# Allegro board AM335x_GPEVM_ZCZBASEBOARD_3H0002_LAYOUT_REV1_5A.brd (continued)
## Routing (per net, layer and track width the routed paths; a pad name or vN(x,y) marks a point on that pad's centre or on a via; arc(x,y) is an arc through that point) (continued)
DDR_A10: length 61
  TOP w0.102: U2.F4 v2(81.8,80.2)
  TOP w0.121: U33.H7 v1(92.98,59.04) ; U34.H7 v1(78.38,59.04)
  LY4 w0.076: 87.29,58 87.54,58 87.69,58.15 93.15,58.15 93.24,58.24
  LY4 w0.133: v1(92.98,59.04) 93.24,58.77 93.24,58.24 ; 87.29,58 85.58,58 85.11,58.47 84.64,58.47 84.63,58.48 82.28,58.48 82.03,58.74 82.03,59.63 81.77,59.89 78.52,59.89 78.38,59.74 v1(78.38,59.04)
  BOTTOM w0.076: 93.68,55.54 93.66,55.56 93.66,56.71 93.3,57.07 92.83,57.07 92.61,57.28 92.61,58.67 v1(92.98,59.04)
  BOTTOM w0.121: R614.2 95.26,54.88 95.26,55.18 95.14,55.31 93.91,55.31 93.68,55.54 ; v1(78.38,59.04) 78.75,59.4 79.01,59.4 79.89,60.29 80.48,60.29 83.35,63.16 84.24,63.16 84.54,63.46 84.54,65.75 84.8,66 86.09,66 86.22,66.13 86.22,67.3 86.09,67.42 84.14,67.42 84.01,67.3 84.01,67.18 83.88,67.05 83,67.05 82.77,67.28 82.4,67.28 82.31,67.19 80.2,67.19 79.69,67.7 79.69,69.18 79.88,69.37 79.88,69.64 80.05,69.8 80.05,74.3 79.92,74.42 79.83,74.42 79.7,74.55 79.7,76.65 80.46,77.4 80.51,77.4 82.21,79.09 82.21,79.79 81.8,80.2 v2(81.8,80.2)
DDR_A11: length 60.8
  TOP w0.121: v1(74.38,59.04) U34.M7 ; U2.F2 82.43,78.77 82.43,78.75 82.58,78.61 82.58,77.63 82.38,77.43 82.38,72.61 82.51,72.49 v1(82.51,72.05) ; v1(88.98,59.04) U33.M7
  LY4 w0.076: 87.29,59.09 87.62,59.09 87.82,58.89 88.84,58.89 v1(88.98,59.04)
  LY4 w0.127: v1(74.38,59.04) 74.1,59.31
  LY4 w0.133: 74.1,59.31 74.1,59.96 74.23,60.08 76.9,60.08 77.02,60.21 77.02,60.69 77.15,60.81 83.07,60.81 83.2,60.69 83.2,59.65 83.32,59.52 85.56,59.52 86,59.09 87.29,59.09 ; v1(72.5,67.5) 72.5,68.46 72.74,68.7 73.12,68.7 73.12,68.71 74.88,68.71 75.5,68.08 75.81,68.08 76.44,68.72 77.5,68.72 79.1,70.32 79.1,70.33 79.74,70.98 82.05,70.98 82.51,71.43 v1(82.51,72.05)
  BOTTOM w0.121: v1(88.98,59.04) 88.59,59.04 88.5,58.94 87.44,58.94 87.31,58.81 87.31,58.69 86.24,57.62 86.24,55.26 R615.2 ; v1(74.38,59.04) 74.38,59.81 73.95,60.24 71.14,60.24 69.2,62.18 69.2,65.31 69.77,65.88 70.88,65.88 v1(72.5,67.5)
DDR_A12: length 61.6
  TOP w0.102: v2(81,79.4) U2.E3
  TOP w0.121: v1(90.58,59.04) U33.K7 ; v1(75.98,59.04) U34.K7
  LY4 w0.076: v1(90.58,59.04) 90.95,59.04 91.02,58.97 91.02,58.62 90.89,58.49 87.58,58.49 87.51,58.56 87.29,58.56
  LY4 w0.133: v1(75.98,59.04) 76.26,59.31 76.47,59.52 77.51,59.52 77.63,59.65 77.63,60.23 77.76,60.36 82.34,60.36 82.66,60.03 82.66,59.12 82.79,58.99 85.36,58.99 85.78,58.56 87.2,58.56 87.2,58.56 87.29,58.56
  BOTTOM w0.121: v1(90.58,59.04) 89.95,58.41 87.9,58.41 87.21,57.72 87.21,54.98 R616.2 ; v1(75.98,59.04) 75.7,59.31 75.7,59.66 74.31,61.04 74.21,61.04 73.98,61.27 73.98,62.54 73.77,62.75 71.08,62.75 70,63.83 70,64.86 70.26,65.12 70.76,65.12 70.89,65 70.89,64.78 71.02,64.65 72.59,64.65 72.71,64.78 72.71,66.49 73.02,66.79 74.26,66.79 74.73,67.27 74.73,68.45 75.16,68.87 75.16,68.88 75.61,69.33 76.7,69.33 77.09,68.94 77.46,68.94 77.78,69.26 77.78,69.51 77.46,69.83 77.46,70.33 79.14,72 79.14,73.14 78.29,73.98 78.29,76.39 81,79.1 v2(81,79.4)
DDR_A13: length 61
  TOP w0.102: U2.H3 v2(83.4,79.4)
  TOP w0.121: v1(88.18,62.24) U33.N3 ; v1(73.58,61.44) U34.N3
  LY4 w0.076: v1(88.18,62.24) 87.81,62.6 87.81,63.39 87.54,63.66 ; v1(73.58,61.44) 73.95,61.8 73.95,62.32 74.22,62.6 74.47,62.6 75.55,63.68 75.55,63.68 75.98,64.12
  LY4 w0.133: 75.98,64.12 76.27,64.41 76.3,64.41 76.39,64.5 78.14,64.5 79.2,65.56 85.64,65.56 87.54,63.66 ; v1(73.58,61.44) 73.12,61.89 73.12,64 73.8,64.68 73.98,64.68 74.99,65.7 76.87,65.7 78.27,67.09 79.23,67.09 79.51,67.37 79.51,67.92 80.03,68.44 v1(80.48,68.44)
  BOTTOM w0.076: v1(88.18,62.24) 88.61,62.66 88.61,64.02
  BOTTOM w0.121: v1(80.48,68.44) 80.95,68.91 81.51,68.91 81.64,69.04 81.64,69.53 81.77,69.66 82.52,69.66 82.65,69.53 82.65,68.82 82.78,68.69 85.94,68.69 86.07,68.82 86.07,69.35 83.79,71.63 83.79,71.74 83,72.53 82.54,72.53 82.41,72.66 82.41,74.87 82.28,74.99 81.03,74.99 80.9,75.12 80.9,75.34 80.9,75.34 80.9,75.71 80.9,75.71 80.9,75.72 81.49,76.31 81.49,77 83.4,78.9 v2(83.4,79.4) ; 88.61,64.02 88.34,64.29 87.96,64.29 87.57,64.68 87.29,64.68 87.03,64.93 87.03,65.55 87.37,65.89 87.37,65.91 87.67,66.2 R617.2
DDR_A14: length 61.6
  TOP w0.102: v2(83.4,80.2) U2.H4
  TOP w0.121: v1(88.05,59.35) 88.31,59.09 88.31,58.9 U33.N7 ; v1(81.34,75.53) 81.01,75.2 81.01,74.18 79.29,72.45 v1(78.07,72.45) ; v1(73.58,59.04) U34.N7
  LY4 w0.076: 87.42,59.35 87.29,59.35
  LY4 w0.127: v1(88.05,59.35) 87.42,59.35 ; 73.3,59.31 v1(73.58,59.04)
  LY4 w0.133: 87.29,59.35 86.11,59.35 85.65,59.8 83.58,59.8 83.45,59.93 83.45,60.91 83.34,61.02 76.88,61.02 76.77,60.91 76.77,60.62 76.74,60.58 76.74,60.58 76.5,60.35 76.03,60.35 75.91,60.46 73.43,60.46 73.3,60.34 73.3,59.31
  BOTTOM w0.121: R618.2 84.49,55.08 84.62,55.21 85.84,55.21 85.97,55.33 85.97,57.77 87.54,59.35 v1(88.05,59.35) ; v2(83.4,80.2) 83.4,80.19 83.79,79.79 83.79,79.56 83.79,79.06 83.7,78.97 83.7,78.56 82.05,76.91 82.05,76.24 v1(81.34,75.53)
  BOTTOM w0.127: v1(73.58,59.04) 71.87,59.04 71.84,59.07 71.44,59.07 67.91,62.6 67.91,65.59 69.94,67.63 70.27,67.63 71.09,68.45 73.26,68.45 74.28,69.47 74.28,69.64 75.44,70.8 76.41,70.8 v1(78.07,72.45)
DDR_A15: length 62.1
  TOP w0.102: v2(80.2,79.4) U2.D3
  TOP w0.121: U34.J7 v1(76.78,59.04) 76.14,59.68 73.18,59.68 69.63,63.23 v1(68.46,63.23) ; v1(91.38,59.04) U33.J7
  LY4 w0.076: 91.88,58.44 91.76,58.31 87.62,58.31 87.62,58.3 87.29,58.3 87.29,58.3
  LY4 w0.133: v1(91.38,59.04) 91.76,59.04 91.88,58.91 91.88,58.44 ; 87.29,58.3 85.68,58.3 85.25,58.73 82.64,58.73 82.38,58.99 82.38,59.7 81.95,60.14 78.04,60.14 77.91,60.01 77.91,59.16 77.79,59.04 v1(76.78,59.04)
  BOTTOM w0.121: v1(91.38,59.04) 90.78,58.43 90.46,58.43 90.23,58.2 90.21,58.2 90.19,58.17 88.35,58.17 87.59,57.42 87.59,55.61 R619.2 ; v1(68.46,63.23) 68.46,65.72 69.99,67.25 70.4,67.25 71.35,68.2 73.37,68.2 75.35,70.18 76.48,70.18 78.63,72.33 78.63,72.83 78.5,72.96 78.06,72.96 77.68,73.34 77.68,76.72 79.59,78.62 79.72,78.62 80.2,79.11 v2(80.2,79.4)
DDR_BA0: length 62.5
  TOP w0.102: U2.C4 v1(79.4,80.2)
  TOP w0.121: v1(93.51,65.14) 94.27,65.14 94.4,65.26 94.4,65.7 R620.2 ; v1(76.78,62.24) U34.J2 77.61,63.07 77.61,64.93 77.16,65.38 74.85,65.38 73.37,66.86 73.37,68.13 72.94,68.56 v1(72.94,69.15) ; U33.J2 v1(91.38,62.24)
  LY4 w0.076: 84.53,63.23 80.38,63.23 80.22,63.38 80.22,63.69 80.17,63.74 79.92,63.74 79.13,62.95 77.54,62.95 77.24,62.65 77.19,62.65 v1(76.78,62.24) ; 92.49,64.58 91.93,64.02 91.93,63.61 91.38,63.06 v1(91.38,62.24) 90.97,62.24 90.84,62.11 90.84,61.81 90.97,61.68 90.97,61.24 90.84,61.11 90.79,61.11 90.6,60.92 87.42,60.92 87.4,60.95
  LY4 w0.127: 84.59,63.24 84.54,63.24 84.53,63.23
  LY4 w0.133: 87.4,60.95 86.95,60.95 86.32,61.58 85.69,61.58 85.3,61.96 85.3,62.84 84.85,63.29 84.63,63.29 84.59,63.24 ; v1(93.51,65.14) 94.02,65.14 94.14,65.01 94.14,64.8 94.02,64.67 93.6,64.67 93.51,64.58 92.49,64.58
  BOTTOM w0.121: v1(79.4,80.2) 78.85,80.2 78.5,79.85 76.46,79.85 75.9,79.29 75.9,78.39 74.41,76.9 74.23,76.9 73.44,77.68 73.26,77.68 73.08,77.5 73.08,77.32 73.87,76.54 73.87,76.36 73.69,76.18 73.51,76.18 72.76,76.93 72.58,76.93 72.4,76.75 72.4,76.57 73.15,75.82 73.15,75.64 72.94,75.42 72.94,74.82 72.81,74.69 71.54,74.69 71.41,74.57 71.41,74.31 71.54,74.19 72.81,74.19 72.94,74.06 72.94,73.8 72.81,73.68 71.82,73.68 71.69,73.55 71.69,73.3 71.82,73.17 72.81,73.17 72.94,73.04 v1(72.94,69.15)
DDR_BA1: length 60.9
  TOP w0.121: v1(90.58,57.44) U33.K8 ; v1(75.6,68.69) 75.6,69.14 76.28,69.81 76.28,70.29 76.4,70.42 80.73,70.42 80.86,70.55 80.86,70.75 80.73,70.88 76.92,70.88 76.8,71 76.8,71.16 76.92,71.28 77.35,71.28 77.61,71.54 77.61,72.77 77.74,72.9 78.89,72.9 80.71,74.71 80.71,75.52 81.16,75.97 81.16,75.98 81.4,76.22 U2.E1 ; v1(75.98,57.44) U34.K8
  LY4 w0.133: v1(90.58,57.44) 90.98,57.04 90.98,56.47 90.98,56.47 90.98,55.52 90.61,55.16 82.49,55.16 82.05,55.59 80.07,55.59 78.62,57.03 76.38,57.03 v1(75.98,57.44)
  BOTTOM w0.076: v1(90.58,57.44) 90.21,57.44 90.16,57.49 90.16,57.9 90.28,58.03 90.89,58.03 91.01,57.9 91.01,57.28 91.01,56.48 91.03,56.46 91.03,55.58 91.07,55.54
  BOTTOM w0.121: v1(75.98,57.44) 76.37,57.83 76.37,58.87 76.37,58.87 76.37,59.2 76.36,59.2 76.36,59.5 74.77,61.09 74.77,61.58 74.78,61.59 74.78,61.6 75.01,61.83 75.05,61.83 75.06,61.84 75.3,61.84 75.3,61.84 75.34,61.84 75.58,62.08 75.58,62.4 76.08,62.9 76.08,64.1 76.64,64.65 76.64,65.04 75.07,66.61 75.07,68.16 v1(75.6,68.69) ; R621.2 92.87,55.03 92.67,55.23 91.38,55.23 91.07,55.54
DDR_BA2: length 61.1
  TOP w0.121: U2.B3 79,79.52 78.59,79.11 78.59,77.99 78.1,77.51 75.69,77.51 74.61,77.51 74.15,77.05 73.16,77.05 71.61,75.5 71.61,72.6 71.36,72.35 68.43,72.35 68.18,72.1 68.18,65.65 73.57,60.26 76.62,60.26 76.78,60.41 v1(76.78,61.44) U34.J3 ; R622.2 94.91,65.42 v1(93.76,64.27) ; v1(91.38,61.44) U33.J3
  LY4 w0.076: 77.15,61.81 77.15,62.33 77.6,62.78 79.23,62.78 79.49,63.03 84.62,63.03 ; 93.28,64.27 92.85,64.27 91.76,63.18 91.76,62.14 91.75,62.13 91.75,62.08 91.38,61.71 v1(91.38,61.44) 91.38,61.07 91.48,60.97 91.48,60.5 91.35,60.37 90.79,60.37 90.47,60.69 87.29,60.69
  LY4 w0.127: 77.15,61.81 v1(76.78,61.44) ; 84.75,63.03 84.62,63.03
  LY4 w0.133: 87.29,60.69 86.84,60.69 86.21,61.32 85.58,61.32 84.97,61.92 84.97,62.8 84.75,63.03 ; v1(93.76,64.27) 93.28,64.27
DDR_CASN: length 61.2
  TOP w0.121: v1(78.38,61.44) U34.G3 ; U2.F1 82.2,77.76 82.13,77.69 82.13,75.14 82.06,75.08 82.06,72 81.94,71.87 79.74,71.87 79.62,71.74 79.62,71.51 79.74,71.39 82.63,71.39 82.76,71.26 82.76,70.19 82.63,70.06 81.9,70.06 81.77,69.94 81.77,69.51 81.9,69.38 82.52,69.38 82.65,69.25 82.65,68.5 82.57,68.42 82.57,67.87 82.45,67.74 79.82,67.74 79.69,67.87 79.69,68.57 79.56,68.69 79.17,68.69 79.04,68.57 v1(79.04,67.78) ; v1(92.98,61.44) U33.G3
  LY4 w0.076: 87.29,59.9 89.71,59.9 89.9,60.1 90.36,60.1 90.58,59.88 92.72,59.88
  LY4 w0.127: 81.19,61.83 79.81,61.83 79.42,61.44 v1(78.38,61.44)
  LY4 w0.133: v1(92.98,61.44) 92.98,60.14 92.72,59.88 ; 81.19,61.83 81.32,61.96 81.32,62.11 81.44,62.24 82.61,62.24 82.74,62.11 82.74,61.96 82.87,61.83 83.86,61.83 83.98,61.7 83.98,60.54 84.11,60.41 86.02,60.41 86.14,60.29 86.14,60.11 86.35,59.9 87.29,59.9
  BOTTOM w0.076: v1(92.98,61.44) 93.35,61.44 93.41,61.49 93.41,62.48 93.53,62.6 93.69,62.6 93.81,62.73 93.81,63.78 93.69,63.91 93.46,63.91 93.33,64.03 93.33,64.46 93.55,64.68 93.56,64.68
  BOTTOM w0.121: 93.56,64.68 93.57,64.7 93.69,64.7 93.95,64.95 93.95,65.32 93.69,65.58 93.5,65.58 R601.2 ; v1(78.38,61.44) 78.42,61.44 78.97,61.99 78.97,62 79,62.02 79,62.64 79.01,62.65 79.01,66.13 79.14,66.25 81.98,66.25 82.1,66.38 82.1,66.81 81.98,66.94 79.14,66.94 79.04,67.04 v1(79.04,67.78)
DDR_CKE: length 62.1
  TOP w0.102: U2.G3 v2(82.6,79.4)
  TOP w0.121: U33.G9 93.71,57.04 93.81,56.93 93.81,56.04 93.69,55.92 93.11,55.92 92.98,56.04 v1(92.98,56.64) ; U34.G9 v1(78.38,56.64) ; R635.2 71.67,58.43 v1(72.35,58.43)
  LY4 w0.127: v1(80.33,69.45) 79.63,69.45 79.63,69.46 79.39,69.46 78.04,68.11 76.82,68.11 76.16,67.45 74.74,67.45
  LY4 w0.133: 74.74,67.45 72.35,65.06 v1(72.35,58.43) 72.35,58.1 73.18,57.27 73.18,57.27 73.41,57.04 73.74,57.04 73.97,56.8 73.97,56.48 74.21,56.24 77.22,56.24 77.62,56.64 v1(78.38,56.64) 79.73,55.28 81.8,55.28 82.22,54.87 91.21,54.87 92.7,56.36 v1(92.98,56.64)
  BOTTOM w0.076: v1(92.98,56.64) 93.35,56.64 93.46,56.53 93.46,55.97 93.26,55.76 93.26,55.58 93.21,55.54
  BOTTOM w0.121: v1(80.33,69.45) 80.33,76.13 80.36,76.17 80.36,76.8 81.6,78.03 81.6,78.03 82.6,79.04 v2(82.6,79.4) ; v1(78.38,56.64) 78.65,56.36 78.65,55.29 R631.1 ; R598.2 93.99,54.42 94.22,54.42 94.35,54.55 94.35,54.93 94.22,55.06 93.26,55.06
  BOTTOM w0.127: 93.21,55.54 93.08,55.4 93.08,55.24 93.26,55.06
DDR_CLK: length 61
  TOP w0.076: 79.56,63.81 79.55,63.8 79.46,63.8 79.22,63.56 79.22,61.65 79.21,61.64 79.21,61.57 79.27,61.51 79.27,61.49
  TOP w0.095: 79.56,63.81 79.66,63.91 79.66,64.06 80.07,64.47 80.07,64.56 80.17,64.67 80.17,66.15 79.79,66.53 78.61,66.53 78.41,66.74 78.03,66.74 77.89,66.88 77.89,68.48 77.42,68.95 76.78,68.95 76.31,68.48 76.31,66.5 76.15,66.33 75.41,66.33 74.66,67.08 74.66,68.47 74.08,69.05 74.08,69.58 74.41,69.91 75.58,69.91 75.81,70.14 75.81,71.85 75.94,71.99 76.88,71.99 77.35,72.47 77.35,73.81 77.7,74.15 79.16,74.15 79.89,74.89 79.89,75.2 80.28,75.58 80.28,77.03 80.48,77.23 80.48,77.43 81.01,77.96 81.01,78.59 U2.D2 ; U34.F7 v1(79.98,59.04) 79.77,59.24 79.77,60.55 79.27,61.05 79.27,61.49 ; R624.2 100.07,59.52 99.94,59.52 99.81,59.39 99.81,59.37 99.68,59.24 99.15,59.24 99.03,59.37 99.03,59.45 98.9,59.57 95.19,59.57 94.86,59.25 94.79,59.25 v1(94.58,59.04) 94.58,59.02 94.2,58.64 U33.F7
  LY4 w0.076: 87.45,57.06 87.45,57.25 87.78,57.58 87.78,57.61 88.01,57.83 93.39,57.83 93.39,57.83 93.92,57.83
  LY4 w0.102: v1(79.98,59.04) 79.96,59.05 79.96,59.25 80.09,59.37 80.59,59.37 80.71,59.25 80.71,58.86 80.56,58.71 80.56,58.56 80.71,58.41 80.71,58.31 81.03,57.98 84.29,57.98 85.36,56.92 87.31,56.92 87.45,57.06 ; v1(94.58,59.04) 94.33,58.79 94.33,58.24 93.92,57.83
DDR_CLKN: length 61.2
  TOP w0.076: 78.99,61.49 78.99,61.51 79.06,61.57 79.06,61.7 79.07,61.71 79.07,63.62 79.35,63.9 79.35,63.99 79.36,64.01
  TOP w0.095: U34.G7 v1(79.18,59.04) 79.49,59.35 79.49,60.44 78.99,60.93 78.99,61.49 ; U33.G7 v1(93.78,59.04) 94.27,59.53 94.74,59.53 95.06,59.85 95.06,59.87 95.07,59.87 99.13,59.87 99.2,59.8 99.69,59.8 100,60.11 R625.2 ; U2.D1 80.6,77.95 80.2,77.54 80.2,77.38 79.97,77.15 79.75,77.15 79.56,76.96 79.56,76.39 79.69,76.26 79.84,76.26 79.97,76.14 79.97,75.67 79.61,75.31 79.61,75.01 79.04,74.43 77.58,74.43 77.08,73.93 77.08,72.58 76.76,72.27 75.82,72.27 75.53,71.97 75.53,70.29 75.42,70.19 74.29,70.19 73.8,69.7 73.8,68.93 74.38,68.35 74.38,66.97 75.3,66.05 76.26,66.05 76.59,66.38 76.59,68.36 76.9,68.67 77.3,68.67 77.61,68.36 77.61,66.76 77.91,66.46 78.29,66.46 78.49,66.25 79.68,66.25 79.89,66.04 79.89,64.78 79.79,64.68 79.79,64.59 79.38,64.18 79.38,64.03 79.36,64.01
  LY4 w0.076: 87.24,57.28 87.25,57.29 87.27,57.29 87.63,57.65 87.63,57.67 87.94,57.99 93.45,57.99 93.45,57.98 93.65,57.98 93.71,58.05
  LY4 w0.102: 87.24,57.28 87.18,57.23 85.48,57.23 84.42,58.29 81.16,58.29 81.01,58.43 81.01,59.4 80.72,59.69 79.7,59.69 79.44,59.43 79.44,59.3 79.35,59.21 79.35,59.21 v1(79.18,59.04) ; v1(93.78,59.04) 94.03,58.79 94.03,58.37 93.71,58.05
DDR_CSN0: length 62.3
  TOP w0.121: U2.H2 83.82,79 84.17,78.65 84.17,75.54 84.52,75.19 84.52,73.52 84.39,73.39 83.84,73.39 83.72,73.27 83.72,71.08 83.84,70.95 84.39,70.95 84.52,70.83 84.52,70.55 84.39,70.42 83.84,70.42 83.72,70.29 83.72,69.88 83.84,69.75 v1(84.45,69.75) ; U33.H2 v1(92.18,62.24) ; v1(73.95,67.6) 73.95,66.83 75.15,65.63 77.61,65.63 78.07,65.18 78.07,64.4 78.29,64.17 78.29,62.95 U34.H2 v1(77.58,62.24)
  LY4 w0.076: 84.57,62.78 79.54,62.78 79.41,62.65 79.41,62.42 79.29,62.29 78.84,62.29 78.53,62.6 77.95,62.6 v1(77.58,62.24) ; 91.76,61.81 91.76,60.57 91.41,60.22 90.66,60.22 90.47,60.42 87.84,60.42 87.84,60.42 87.29,60.42
  LY4 w0.127: 86.75,60.42 86.75,60.42 87.13,60.42 ; 91.76,61.81 v1(92.18,62.24)
  LY4 w0.133: 84.57,62.78 84.7,62.65 84.7,61.84 85.47,61.06 86.11,61.06 86.73,60.43 86.74,60.43 86.75,60.42 87.29,60.42 ; v1(84.45,69.75) 84.77,70.07 84.77,70.78 84.57,70.98 84.01,70.98 83.88,70.85 83.88,69.86 83.43,69.4 82.59,69.4 81.47,70.52 79.79,70.52 77.68,68.41 76.75,68.41 76.14,67.8 75.32,67.8 75.07,68.06 74.41,68.06 v1(73.95,67.6)
  BOTTOM w0.076: v1(92.18,62.24) 91.81,61.86 90.79,61.86 90.66,61.99 90.66,62.6 90.95,62.88 90.95,63.99 90.66,64.27 90.66,64.55 90.79,64.68 90.91,64.68
  BOTTOM w0.121: R599.2 91.35,65.7 91.35,65.12
  BOTTOM w0.127: 90.91,64.68 91.35,65.12
DDR_D0: length 35.3
  TOP w0.102: v2(87.4,79.4) U2.M3
  TOP w0.121: U33.B3 v1(97.78,61.44)
  BOTTOM w0.121: v2(87.4,79.4) 87.4,77.34 87.72,77.02 87.72,75.11 88.16,74.66 89.92,74.66 91.43,73.16 91.43,69.48 91.68,69.23 94.64,69.23 94.87,69 94.87,67.47 95.12,67.22 95.64,67.22 95.9,67.47 95.9,68.92 96.15,69.18 96.5,69.18 96.96,68.71 96.96,67.07 96.71,66.81 95.85,66.81 95.59,66.56 95.59,66.17 95.85,65.91 97.12,65.91 97.25,65.78 97.38,65.78 99.73,63.44 99.73,62.24 98.93,61.44 v1(97.78,61.44)
DDR_D1: length 35.9
  TOP w0.102: v2(87.4,80.2) U2.M4
  TOP w0.121: v1(96.98,59.04) U33.C7 ; v1(91.92,71.11) 92.37,71.11 92.39,71.08 v1(94.25,71.08)
  BOTTOM w0.121: v1(91.92,71.11) 91.92,73.02 89.8,75.14 89.8,76.17 89.1,76.87 88.56,76.87 87.79,77.63 87.79,79.79 87.4,80.19 v2(87.4,80.2) ; v1(94.25,71.08) 97.93,71.08 98.56,70.45 98.56,66.66 99.63,65.59 100.19,65.59 101.36,64.43 101.36,60.24 100.65,59.52 97.47,59.52 v1(96.98,59.04)
DDR_D2: length 35.4
  TOP w0.121: U2.N1 87.8,77.27 88.19,76.87 89.11,76.87 89.9,76.08 90.11,76.08 95.41,70.78 95.44,70.78 95.9,70.32 96.63,70.32 98.69,68.26 98.69,65.24 98.94,64.98 99.66,64.98 99.91,65.24 99.91,68.97 100.16,69.23 100.72,69.23 100.98,68.97 100.98,63.23 100.72,62.98 96.93,62.98 U33.C2
DDR_D3: length 35.8
  TOP w0.121: v1(96.98,57.44) U33.C8
  TOP w0.127: v1(99.33,67.02) 99.33,68.15 96.7,70.78 95.81,70.78 90.09,76.51 89.84,76.51 89.22,77.13 89.21,77.13 89.09,77.25 88.76,77.25 88.26,77.75 88.26,78.05 88.26,78.06 88.26,78.54 U2.N2
  BOTTOM w0.127: v1(99.33,67.02) 101.53,67.02 102.09,66.46 102.09,58.33 101.54,57.77 101.21,57.77 100.7,57.26 99.57,57.26 98.58,58.25 97.41,58.25 96.98,57.83 v1(96.98,57.44)
DDR_D4: length 35.9
  TOP w0.102: U2.N3 v2(88.2,79.4)
  TOP w0.127: U33.E3 93.97,60.82 93.97,60.26 94.3,59.93 94.68,59.93 95.38,60.63 v1(95.38,61.44)
  BOTTOM w0.121: v2(88.2,79.4) 88.2,78.18 90.21,76.17 90.21,75.37 92.37,73.21 92.37,69.61 92.47,69.51 96.53,69.51 97.22,68.82 97.22,66.38 100.09,63.51 100.09,62.19 98.77,60.87 97.78,60.87 97.52,61.12 97.52,61.14 96.55,62.11 95.82,62.11 95.66,61.96 95.66,61.71 v1(95.38,61.44)
DDR_D5: length 35.8
  TOP w0.102: U2.N4 v2(88.2,80.2)
  TOP w0.121: v1(95.38,57.44) U33.E8
  BOTTOM w0.121: v1(95.38,57.44) 94.98,57.83 94.98,59.22 95.9,60.13 95.9,61 96.15,61.25 96.58,61.25 97.27,60.57 99.15,60.57 100.39,61.8 100.39,63.59 97.57,66.41 97.57,68.95 96.46,70.06 93.48,70.06 92.7,70.85 92.7,73.49 91.81,74.38 91.81,75.21 88.59,78.42 88.59,79.81 v2(88.2,80.2)
DDR_D6: length 35.3
  TOP w0.121: v1(96.33,60.78) 96.33,61.15 96.18,61.3 96.18,62.24 U33.D2
  TOP w0.305: U2.P3 v2(89,79.4)
  BOTTOM w0.121: v2(89,79.4) 89,78.59 92.11,75.48 92.11,74.66 92.52,74.26 93.92,74.26 94.3,73.87 94.3,72.94 94.07,72.71 93.26,72.71 92.98,72.43 92.98,71.13 93.79,70.32 97.17,70.32 97.89,69.59 97.89,67.01 97.89,66.59 97.9,66.58 97.9,66.48 100.03,64.36 100.7,63.69 100.7,60.77 100.16,60.24 96.87,60.24 v1(96.33,60.78)
DDR_D7: length 35.9
  TOP w0.102: U2.P4 v2(89,80.2)
  TOP w0.121: v1(95.38,59.04) U33.E7
  BOTTOM w0.121: v2(89,80.2) 89.39,79.81 89.39,78.64 90.78,77.25 90.78,77.24 92.54,75.48 92.54,75.2 93.22,74.52 94.08,74.52 94.68,73.93 94.68,72.73 94.32,72.38 93.92,72.38 93.38,71.84 93.38,71.26 94.07,70.57 97.49,70.57 98.14,69.92 98.14,66.7 101.05,63.79 101.05,60.54 100.44,59.93 96.28,59.93 v1(95.38,59.04)
DDR_D8: length 35.4
  TOP w0.121: U2.J1 84.6,77.64 84.54,77.58 84.54,75.65 84.9,75.3 84.9,73.24 84.77,73.11 84.14,73.11 84.01,72.99 84.01,72.63 84.14,72.5 84.9,72.5 85.03,72.38 85.03,72.05 84.9,71.92 84.11,71.92 83.98,71.79 83.98,71.41 84.11,71.28 84.92,71.28 85.05,71.16 85.05,69.43 84.92,69.31 83.83,69.31 83.7,69.18 83.7,66.48 83.58,66.36 82.13,66.36 82,66.48 82,67.32 81.88,67.45 81.19,67.45 81.06,67.32 81.06,65.39 81.19,65.26 83.58,65.26 83.7,65.14 83.7,64.96 83.58,64.83 81.24,64.83 81.11,64.71 81.11,64.55 81.24,64.43 84.24,64.43 84.37,64.3 84.37,63.49 83.98,63.1 82.78,63.1 82.45,62.77 82.45,62.5 82.78,62.17 U34.B3
DDR_D9: length 35.8
  TOP w0.121: v1(90.89,70.4) 89.7,70.4 88.24,68.93 88.22,68.93 87.42,68.14 87.42,67.26 86.93,66.77 86.93,65.37 87.21,65.09 87.21,59.92 87.08,59.79 86.91,59.79 86.78,59.67 86.78,57.09 86.65,56.96 85.05,56.96 84.92,57.09 84.92,59.02 84.8,59.14 83.98,59.14 83.91,59.22 82.13,59.22 81.98,59.07 U34.C7
  TOP w0.127: U2.K1 85.4,77.96 85.6,77.77 85.6,77.76 85.65,77.71 85.65,77.68 85.7,77.63 85.7,76.1 85.25,75.65 85.25,74.1 86.7,72.66 v1(87.32,72.66)
  BOTTOM w0.127: v1(87.32,72.66) 88.11,71.87 89.83,71.87 89.95,71.74 89.95,70.52 90.08,70.4 v1(90.89,70.4)
DDR_D10: length 35.4
  TOP w0.121: U34.C2 82.23,62.38 82.23,62.13 82.41,61.95 82.41,61.28 82.54,61.15 84.49,61.15 84.62,61.28 84.62,64.65 84.49,64.78 84.19,64.78 84.06,64.91 84.06,65.44 83.93,65.57 81.52,65.57 81.39,65.7 81.39,65.9 81.52,66.03 83.93,66.03 84.06,66.15 84.06,68.92 84.19,69.05 85.2,69.05 85.33,69.18 85.33,72.86 85.46,72.99 85.89,72.99 86.01,72.86 86.01,72.45 86.14,72.32 87.03,72.32 87.14,72.21 87.51,72.21 87.62,72.32 88.38,72.32 88.51,72.45 88.51,73.29 88.38,73.42 86.3,73.42 85.51,74.21 85.51,75.51 85.64,75.64 85.84,75.64 85.96,75.77 85.96,77.69 85.88,77.77 85.88,77.81 85.83,77.86 85.83,78.59 85.41,79 U2.K2
DDR_D11: length 35.7
  TOP w0.102: v2(85.8,79.4) U2.K3
  TOP w0.121: U34.C8 82.37,58.23 84.26,58.23 84.39,58.1 84.39,56.53 84.52,56.4 87.18,56.4 87.31,56.53 87.31,58.33 87.59,58.61 87.59,59.63 87.72,59.75 87.72,65.42 87.46,65.68 87.46,66.48 87.98,67 87.98,67.19 87.98,67.98 88.43,68.43 88.72,68.43 v1(89.77,69.48)
  BOTTOM w0.121: v1(89.77,69.48) 88.35,69.48 86.44,71.39 86.44,71.5 86.37,71.57 86.37,73.05 86.37,73.05 86.37,73.79 86.59,74 86.59,74.44 86.37,74.66 86.37,74.74 85.71,75.4 85.53,75.4 84.81,76.12 84.81,76.63 85.76,77.58 85.76,78.97 85.8,79.01 v2(85.8,79.4)
DDR_D12: length 35.8
  TOP w0.102: U2.K4 v2(85.8,80.2)
  TOP w0.121: U34.E3 80.38,60.06 80.5,59.93 84.59,59.93 84.64,59.98 85.56,59.98 85.69,59.85 85.89,59.85 86.02,59.98 86.02,59.98 86.09,60.06 86.09,66.84 85.89,67.04 85.89,67.91 86.01,68.02 86.01,68.03 88.08,70.1 88.31,70.1 88.53,70.33 v1(88.53,70.78)
  BOTTOM w0.121: v2(85.8,80.2) 85.86,80.2 86.21,79.86 86.21,79.56 86.21,77.68 85.95,77.43 85.95,75.96 86.88,75.03 86.88,74.87 87.1,74.65 87.1,73.9 87.2,73.8 87.51,73.8 87.64,73.67 87.64,73.27 87.51,73.14 87.1,73.14 86.88,72.92 86.88,72.84 86.88,72.84 86.88,71.79 87.12,71.54 89.55,71.54 89.67,71.41 89.67,70.4 89.55,70.27 89.04,70.27 v1(88.53,70.78)
DDR_D13: length 35.9
  TOP w0.102: v2(86.6,79.4) U2.L3
  TOP w0.121: v1(90.41,70.85) 89.78,70.85 88.52,69.6 88.29,69.6 86.52,67.82 86.52,67.43 86.67,67.27 86.67,65.27 86.96,64.98 86.96,60.17 86.83,60.05 86.8,60.05 86.52,59.77 86.52,57.85 86.4,57.72 85.3,57.72 85.18,57.85 85.18,59.32 85.05,59.45 81.32,59.45 80.78,58.91 80.78,58.24 U34.E8
  BOTTOM w0.121: v1(90.41,70.85) 90.41,71.72 89.79,72.34 89.45,72.34 89.32,72.47 89.32,73.6 89.19,73.72 88.38,73.72 88.02,74.08 88.02,74.08 87.13,74.97 87.13,76.44 87.01,76.57 86.73,76.57 86.6,76.69 v2(86.6,79.4)
DDR_D14: length 35.9
  TOP w0.102: U2.L4 v2(86.6,80.2)
  TOP w0.127: v1(82.21,68.85) 82.21,68.4 81.8,67.99 80.29,67.99 80.03,68.26 80.03,68.62 80.04,68.63 80.04,68.85 79.91,68.97 78.72,68.97 78.6,68.85 78.6,67.59 79.12,67.07 80.56,67.07 80.68,66.94 80.68,64.3 80.38,64 80.38,63.91 80.19,63.71 80.12,63.71 80,63.59 80,63.16 80.1,63.05 80.76,63.05 U34.D2
  LY4 w0.133: v1(82.21,68.85) 86.3,68.85 87.06,69.61 87.06,70.5 88.61,72.05 88.61,72.33 88.6,72.34 88.6,73.01 88.72,73.14 v1(89.88,73.14)
  BOTTOM w0.121: v1(89.88,73.14) 90.61,73.14 90.74,73.27 90.74,73.49 89.82,74.41 88.06,74.41 87.46,75 87.46,76.92 87.15,77.24 87.15,77.24 87.01,77.38 87.01,79.79 v2(86.6,80.2)
DDR_D15: length 35.8
  TOP w0.121: U34.E7 80.38,58.96 80.43,59.01 80.43,59.47 80.69,59.73 85.3,59.73 85.43,59.6 85.43,58.28 85.56,58.15 86.14,58.15 86.27,58.28 86.27,59.88 86.42,60.03 86.42,67.17 86.26,67.32 86.26,67.92 88.19,69.85 88.41,69.85 89.67,71.11 89.67,71.11 90.13,71.56 92.09,71.56 92.21,71.69 92.21,72.98 90.69,74.51 88.91,74.51 87.97,74.51 87.44,75.03 87.44,76.71 87,77.16 U2.M1
DDR_DQM0: length 35.6
  TOP w0.121: v1(97.78,59.04) U33.B7
  TOP w0.127: v1(93.89,71.67) 90.79,74.76 88.88,74.76 88.88,74.76 88.68,74.76 88.68,74.76 88.07,74.76 87.7,75.14 87.7,77.01 87.39,77.31 87.39,78.87 87.27,79 U2.M2
  BOTTOM w0.121: v1(93.89,71.67) 94.35,71.67 94.68,71.33 98.3,71.33 98.82,70.81 98.82,66.79 99.22,66.38 101.18,66.38 101.74,65.82 101.74,59.78 100.85,58.89 98.32,58.89 98.18,59.04 v1(97.78,59.04)
DDR_DQM1: length 35.9
  TOP w0.121: U34.B7 83.09,58.95 83.71,58.95 83.92,58.74 84.54,58.74 84.67,58.61 84.67,56.76 84.77,56.65 86.93,56.65 87.03,56.76 87.03,58.57 87.16,58.69 87.26,58.69 87.39,58.82 87.39,59.71 87.46,59.79 87.46,65.21 87.18,65.5 87.18,66.66 87.73,67.21 87.73,68.09 88.33,68.68 88.34,68.68 89.65,69.98 90.23,69.98 90.53,69.68 v1(90.54,69.68)
  TOP w0.127: v1(85.25,76.3) 85.25,76.95 85.44,77.13 85.44,77.56 85.42,77.58 85.42,77.62 85,78.04 85,78.59 84.6,78.99 U2.J2
  BOTTOM w0.121: v1(90.54,69.68) 90.22,70 88.19,70 88.05,70.14 88.05,71.16 87.92,71.28 87.02,71.28 86.62,71.68 86.62,72.94 86.63,72.95 86.63,73.65 86.84,73.86 86.84,74.55 86.63,74.76 86.63,74.93 85.7,75.85 85.7,75.86 v1(85.25,76.3)
DDR_DQS0: length 35.6
  TOP w0.095: U2.P1 88.6,77.83 88.81,77.62 89.06,77.62 89.21,77.47 89.33,77.47 89.39,77.41 89.41,77.41 90.02,76.8 90.56,76.8 93.13,74.23 94.98,74.23 95.39,73.82 95.39,71.94 96.02,71.31 101.21,71.31 102.73,69.79 102.73,63.5 101.52,62.29 100.29,62.29 99.74,61.75 99.45,61.75 99.33,61.62 99.33,61.33 99.1,61.1 98.59,61.1 98.46,60.97 98.46,60.72 98.34,60.59 98.06,60.59 97.93,60.72 97.93,60.9 97.8,61.02 97.6,61.02 97.47,60.9 97.47,60.72 97.34,60.59 97.08,60.59 96.94,60.74 96.94,60.92 96.82,61.04 96.82,61.25 96.99,61.42 96.99,62.17 96.87,62.29 96.7,62.29 96.58,62.17 U33.C3
DDR_DQS1: length 35.3
  TOP w0.095: U2.L1 86.2,77.85 86.34,77.7 86.34,76.88 86.37,76.85 86.37,76.84 86.68,76.53 86.68,76.36 86.55,76.24 86.45,76.24 86.32,76.11 86.32,75.83 86.45,75.7 86.55,75.7 86.68,75.58 86.68,75.37 86.55,75.25 86.3,75.25 86.17,75.12 86.17,74.94 86.3,74.81 86.55,74.81 86.68,74.69 86.68,74.33 87.18,73.82 90.52,73.82 91.3,73.05 91.3,72.42 91.19,72.3 89.51,72.3 88.82,71.61 86.76,71.61 86.73,71.59 86.45,71.31 86.45,70.75 86.75,70.45 86.99,70.45 87.08,70.35 87.08,70.03 86.97,69.91 86.18,69.91 85.89,69.62 85.89,68.89 85.67,68.67 84.73,68.67 84.44,68.38 84.44,65.87 84.8,65.52 85.28,65.52 85.41,65.39 85.41,60.84 85.28,60.72 81.66,60.72 81.48,60.9 81.48,61.69 81.62,61.84 U34.C3
DDR_DQSN0: length 35.9
  TOP w0.095: U33.D3 95.78,61.5 95.8,61.48 95.8,60.69 96.18,60.31 98.72,60.31 100.42,62.01 101.64,62.01 103.01,63.38 103.01,69.9 101.32,71.59 96.14,71.59 95.67,72.06 95.67,73.94 95.1,74.51 93.24,74.51 90.68,77.08 90.13,77.08 89.6,77.61 89.6,77.66 89.42,77.83 89.4,77.83 89.38,77.85 89.29,77.85 89.09,78.05 89.09,78.07 89.07,78.09 89.07,78.53 U2.P2
DDR_DQSN1: length 35.7
  TOP w0.095: U2.L2 86.63,78.57 86.63,76.97 86.98,76.62 86.98,74.42 87.3,74.1 90.64,74.1 91.58,73.16 91.58,72.3 91.3,72.02 89.63,72.02 88.91,71.31 86.85,71.31 86.73,71.19 86.73,70.86 86.84,70.75 87.08,70.75 87.36,70.47 87.36,69.91 87.08,69.63 86.3,69.63 86.17,69.51 86.17,68.77 85.79,68.39 84.85,68.39 84.72,68.26 84.72,65.99 84.91,65.8 85.4,65.8 85.69,65.51 85.69,60.73 85.4,60.44 81.55,60.44 81.18,60.81 U34.D3
DDR_ODT: length 59
  TOP w0.121: U2.G1 83,77.82 82.94,77.77 82.94,77.23 82.64,76.92 82.64,73.6 82.83,73.42 82.83,72.62 83.01,72.43 83.01,70.05 83.02,70.05 83.02,68.68 83.02,68.68 v1(83.02,68.24) ; v1(88.12,64.68) 88.4,64.4 92.41,64.4 v1(92.98,63.84) U33.G1
  TOP w0.127: v1(78.27,65.87) 78.78,65.37 U34.G1
  LY4 w0.133: v1(88.12,64.68) 88.12,65.07 87.01,66.19 78.58,66.19 v1(78.27,65.87) 78.27,66.44 78.4,66.57 82,66.57 82.13,66.69 82.13,67.02 82,67.14 79.92,67.14 79.79,67.27 79.79,67.7 80.01,67.92 82.17,67.92 83.27,66.81 85.64,66.81 85.76,66.94 85.76,67.22 85.64,67.35 84.26,67.35 84.14,67.47 84.14,67.75 84.26,67.88 86.24,67.88 86.37,68.01 86.37,68.39 86.24,68.52 83.75,68.52 83.47,68.24 v1(83.02,68.24)
  BOTTOM w0.121: R623.2 92.17,66.2 92.3,66.08 92.3,65.25 92.47,65.09 92.94,65.09 93.15,64.87 93.15,64.65 93.03,64.53 92.29,64.53 92.04,64.78 91.86,64.78 91.73,64.65 91.73,64.1 91.86,63.97 92.11,63.97 92.24,63.84 92.24,63.55 92.37,63.43 92.57,63.43 v1(92.98,63.84)
DDR_RASN: length 62.2
  TOP w0.102: U2.G4 v2(82.6,80.2)
  TOP w0.121: U33.F3 v1(93.78,61.44) ; v1(79.98,61.44) U34.F3 ; v1(96.94,65.47) 97.52,65.47 97.65,65.59 97.65,66.08 97.52,66.2 R600.2
  TOP w0.127: v1(82.59,66.84) v1(83.25,67.5)
  LY4 w0.076: v1(93.78,61.44) 93.78,60.97 93.91,60.84 94.04,60.84 94.17,60.72 94.17,59.56 94.04,59.43 90.43,59.43 90.36,59.36 90.05,59.36 89.69,59.73 87.74,59.73 87.66,59.64 87.37,59.64
  LY4 w0.127: 87.29,59.64 87.37,59.64
  LY4 w0.133: 87.29,59.64 86.18,59.64 85.71,60.11 83.86,60.11 83.73,60.24 83.73,61.31 83.6,61.44 v1(79.98,61.44) ; v1(96.94,65.47) 95.97,64.5 95.24,64.5 94.73,63.99 94.73,62.38 v1(93.78,61.44)
  BOTTOM w0.121: v2(82.6,80.2) 82.99,79.81 82.99,78.98 81.16,77.15 81.16,76.61 80.61,76.06 80.61,74.48 80.74,74.36 81.94,74.36 82.06,74.23 82.06,71.86 82.32,71.6 83.46,71.6 85.2,69.86 85.2,69.68 84.47,68.95 83.06,68.95 82.9,69.1 82.9,69.79 82.78,69.91 81.51,69.91 81.39,69.79 81.39,69.29 81.26,69.16 80.84,69.16 80.69,69.01 80.39,69.01 80.02,68.64 80.02,67.8 80.15,67.68 82.82,67.68 82.99,67.5 v1(83.25,67.5) ; v1(79.98,61.44) 81.2,61.44 82.79,63.03 82.79,64.38 82.91,64.5 82.92,64.5 83.04,64.63 83.04,66.38 v1(82.59,66.84)
DDR_RESETN: length 55.3
  TOP w0.102: v2(83.35,77.63) 83.35,78.65 83,79 U2.G2
  TOP w0.121: v1(88.18,63.04) U33.N2 ; U34.N2 v1(73.58,62.24) 73.29,62.52 73.29,63.13 72.62,63.8 72.62,64.78 72.39,65.01 71.41,65.01 70.67,65.75 70.67,69.89 70.93,70.14 71.97,70.14 72.22,70.4 72.22,71.08 72.48,71.33 74.05,71.33 74.28,71.56 74.28,73.88 74.54,74.14 76.06,74.14 76.3,73.9 v1(76.3,73.46)
  LY4 w0.076: 87.67,64.65 87.67,64.5 87.77,64.4 87.77,63.71 88.18,63.31 88.18,63.04 v1(88.18,63.04) ; v1(73.58,62.24) 74.75,63.4 74.75,64.13 75.04,64.43 75.25,64.43 75.49,64.67
  LY4 w0.127: 75.69,64.87 75.69,64.99 75.95,65.25 76.05,65.25
  LY4 w0.133: v2(83.35,77.63) 83.35,77.24 83.4,77.19 83.4,75.3 81.88,73.77 80.57,73.77 80.44,73.9 80.44,74.48 80.31,74.61 80.06,74.61 79.93,74.48 79.93,73.9 79.81,73.77 79.55,73.77 79.42,73.9 79.42,74.48 79.3,74.61 79.04,74.61 78.92,74.48 78.92,73.9 78.79,73.77 78.54,73.77 78.41,73.9 78.41,74.48 78.28,74.61 78.03,74.61 77.9,74.48 77.9,73.9 77.77,73.77 76.61,73.77 v1(76.3,73.46) ; 87.67,64.65 86.5,65.82 79.01,65.82 78.44,65.25 76.05,65.25 ; 75.49,64.67 75.69,64.87
  BOTTOM w0.121: R630.1 87.93,63.04 v1(88.18,63.04)
DDR_WEN: length 62
  TOP w0.121: R602.2 v1(95.92,65.44) ; U34.H3 v1(77.58,61.44) 77.58,60.31 77.23,59.96 73.47,59.96 67.73,65.69 v1(67.73,66.71) ; v1(69.96,68.52) 69.96,70.9 70.9,71.84 72.15,71.84 72.55,72.25 72.55,74.03 72.68,74.15 73.69,74.15 73.97,74.43 73.97,75.57 75.4,77 78.42,77 78.77,77.35 78.77,77.4 79.38,78.01 79.38,78.87 79.25,79 U2.B2 ; v1(92.18,61.44) U33.H3
  LY4 w0.076: v1(77.58,61.44) 77.95,61.81 79.44,61.81 79.56,61.94 79.56,62.37 79.8,62.6 84.23,62.6 84.42,62.42 ; 94.47,64.25 94.47,63.55 93.78,62.85 93.2,62.85 93.1,62.75 92.77,62.75 92.55,62.53 92.55,61.8 v1(92.18,61.44) 92.18,61.07 92.26,60.98 92.26,60.67 91.65,60.06 90.61,60.06 90.42,60.25 89.75,60.25 89.66,60.16 87.4,60.16
  LY4 w0.133: v1(95.92,65.44) 95.54,65.06 95.29,65.06 94.47,64.25 ; 84.42,62.42 84.42,60.92 84.66,60.67 86.12,60.67 86.4,60.39 86.4,60.3 86.55,60.16 87.4,60.16
  BOTTOM w0.121: v1(67.73,66.71) 68.04,67.02 68.04,67.04 69.52,68.52 v1(69.96,68.52)
EECS: length 6.9
  TOP w0.121: U61.1 9.94,87.73 11.78,85.89 11.78,84.91 11.77,84.91 U58.63
EEDATA: length 7.1
  TOP w0.121: U58.61 12.77,84.85 12.42,85.2 12.42,86.18 11.49,87.11 11.49,87.39 11.47,87.42 R587.1 12.48,88.94 U61.3
EESK: length 7
  TOP w0.121: U58.62 12.27,84.83 12.03,85.07 12.03,86 11.94,86.09 11.94,86.1 10.81,87.24 10.81,88.61 11.21,89.01 U61.2
EMU2: length 53.9
  TOP w0.121: 24,86.65 v1(22.14,86.65) ; R76.1 66.18,94.02 65.73,94.46 64.94,94.46 64.12,95.29 60.34,95.29 59.49,94.44 57.37,94.44 56.03,93.11 48.22,93.11 47.24,92.13 32.7,92.13 31.75,91.19 27.94,91.19 26.58,89.83 21.63,89.83 v1(21.12,89.32)
  BOTTOM w0.121: v1(22.14,86.65) 21.6,86.65 21.12,87.13 v1(21.12,89.32)
EMU3: length 40.2
  TOP w0.121: J2.18 31.66,86.65 32.04,87.03 32.04,89.78 33.27,91 35.21,91 35.62,90.59 46.9,90.59 48.68,92.37 57.23,92.37 57.31,92.45 61.59,92.45 62.71,93.57 63.48,93.57 R77.1
EMU4: length 62.5
  TOP w0.121: R78.1 70.75,91.22 70.05,91.93 68.48,91.93 67.66,92.75 65.65,92.75 64.96,93.44 64.57,93.44 63.86,94.14 62.39,94.14 61.31,93.06 59.73,93.06 59.22,93.57 57.19,93.57 56.24,92.61 48.55,92.61 47.19,91.25 32.96,91.25 31.53,89.83 27.47,89.83 26.2,88.56 20.87,88.56 v1(20.1,89.32) ; 24,85.38 v1(22.14,85.38)
  BOTTOM w0.121: v1(20.1,89.32) 20.1,86.65 21.37,85.38 v1(22.14,85.38)
EMU_RSTN: length 6.4
  TOP w0.121: R517.1 v1(22.14,87.92) 24,87.92
  BOTTOM w0.121: C260.1 23.53,86.65 23.15,87.03 23.15,87.54 22.77,87.92 v1(22.14,87.92)
EMU_USB_DM: length 30.6
  TOP w0.114: J40.2 4.93,100.13 5.11,99.94 7.47,99.94 7.67,100.14 ; 7.67,100.14 U57.5 ; 7.67,100.14 7.86,99.94 8.69,99.94 8.7,99.94 9.46,99.94 10.05,99.34 10.05,98.71 v1(10.33,98.43)
  TOP w0.121: U58.7 v1(10.52,79.02)
  BOTTOM w0.114: v1(10.52,79.02) 10.17,78.68 10.02,78.68 9.66,79.03 9.66,80.66 10.2,81.19 10.2,83.22 9.31,84.11 9.31,96.73 10.05,97.48 10.05,98.15 v1(10.33,98.43)
EMU_USB_DP: length 30.8
  TOP w0.114: 8.67,99.5 8.82,99.66 9.34,99.66 9.77,99.23 9.77,98.71 v1(9.49,98.43) ; 8.67,99.5 8.51,99.66 5.11,99.66 4.93,99.48 J40.3 ; 8.67,99.5 U57.3
  TOP w0.121: U58.8 10.26,78.52 v1(10.6,78.18)
  BOTTOM w0.114: v1(10.6,78.18) 10.38,78.4 9.9,78.4 9.38,78.92 9.38,80.77 9.92,81.31 9.92,83.11 9.03,84 9.03,96.85 9.77,97.59 9.77,98.15 v1(9.49,98.43)
ENZ_KALDO_1P8V: length 9.6
  TOP w0.102: 77.34,79.83 77.76,79.41 78.33,79.41 78.64,79.72 78.64,80.24 U2.B4
  TOP w0.121: 77.34,79.83 76.63,79.83 75.97,79.17 72,79.17 R48.2
ETH_INTN: length 118.5
  TOP w0.121: R404.1 80.91,103.57 80.91,105.47 80.01,106.37 80.01,107.25 78.56,108.7 66.59,108.7 66.08,108.19 v1(64.24,108.19) ; v1(63.82,102.91) 63.32,103.41 57.35,103.41 56.26,104.49 54.02,104.49 51.45,101.92 49.64,101.92 46.8,99.07 43.12,99.07 42.38,98.34 34.5,98.34 34.3,98.54 v1(32.35,98.54) ; U25.5 28.99,55.76 v1(28.85,55.89)
  BOTTOM w0.121: v1(64.24,108.19) 64.24,107.75 64.17,107.68 64.17,105.17 65.16,104.18 65.16,103.67 64.4,102.91 v1(63.82,102.91) ; v1(32.35,98.54) 32.35,98.1 32.4,98.05 32.4,91.8 32.32,91.73 32.32,87.16 26.9,81.74 26.9,67.51 25.14,65.75 24.09,65.75 22.39,64.05 22.39,62.14 23.15,61.38 23.15,58.46 23.53,58.08 24.8,58.08 R409.1 25.59,58.84 25.88,58.54 25.88,57.63 26.5,57.01 26.5,56.04 27.01,55.54 28.15,55.54 28.33,55.71 28.34,55.71 28.52,55.89 v1(28.85,55.89)
ETH_MDIO_CLK: length 134
  TOP w0.121: R433.1 91.1,98.97 v1(91.35,99.22) ; U25.1 30.09,57.38 30.09,57.67 v1(29.65,58.1)
  LY3 w0.133: v1(33.11,107.4) 33.38,107.67 34.16,107.67 34.29,107.54 42.62,107.54 46.98,111.9 51.93,111.9 52.23,111.59 86.22,111.59 86.99,112.37 87.34,112.37 87.73,112.75 89.02,112.75 90.26,111.52 v1(92.62,111.52)
  BOTTOM w0.121: v1(33.11,107.4) 33.56,106.95 33.56,99.57 33.03,99.04 33.03,97.96 32.9,97.83 32.9,91.55 32.82,91.47 32.82,86.82 27.72,81.72 R407.2 28.22,59.48 28.22,59.11 28.68,58.65 29.08,58.65 29.63,58.1 v1(29.65,58.1) ; v1(92.62,111.52) 92.62,112 92.49,112.13 92.11,112.13 91.98,112 91.98,110.85 92.1,110.73 92.75,110.73 92.87,110.61 92.87,110.37 92.75,110.25 92.1,110.25 91.98,110.13 91.98,109.29 92.98,108.29 92.98,102.59 92.46,102.07 92.46,102.07 91.71,101.31 91.71,99.58 91.66,99.54 91.66,99.54 v1(91.35,99.22)
ETH_MDIO_DATA: length 134.6
  TOP w0.121: U25.48 30.98,58.83 30.77,59.04 30.77,59.84 v1(30.53,60.08) ; R434.1 v1(93.68,100.88)
  LY3 w0.133: v1(95.92,111.04) 95.47,111.04 95.42,110.98 90.05,110.98 89.75,110.68 84.64,110.68 84.34,110.98 60.79,110.98 60.29,110.48 60.21,110.48 59.67,109.94 50.28,109.94 47.56,107.23 v1(33.97,107.23)
  BOTTOM w0.121: v1(33.97,107.23) 33.97,99.23 33.28,98.54 33.28,97.73 33.15,97.6 33.15,86.7 28.54,82.08 28.54,63.36 R408.1 30.9,60.44 v1(30.53,60.08) ; v1(95.92,111.04) 95.67,110.78 95.67,107.86 95.8,107.73 96.2,107.73 96.33,107.86 96.33,109.99 96.46,110.12 96.73,110.12 96.86,109.99 96.86,103.75 93.99,100.88 v1(93.68,100.88)
ETH_RBIAS: length 4.6
  TOP w0.121: v1(28.36,54.52) 28.76,54.11 29.46,54.11 29.51,54.16 U25.9
  BOTTOM w0.381: R406.2 29.43,55.66 29.09,55.32 28.68,55.32 28.36,55 v1(28.36,54.52)
ETH_REFCLK: length 148.7
  TOP w0.121: U25.25 36.87,52.96 36.92,52.91 36.92,52.91 37.1,52.74 v1(37.12,52.74) ; R432.1 80.45,108.11 78.94,109.62 65.91,109.62 65.7,109.41 51.8,109.41 51.67,109.28 51.67,108.02 51.31,107.66 50.83,107.66 50.7,107.53 50.7,105.14 50.57,105.02 39.25,105.02 38.77,105.5 38.77,109.46 39.38,110.07 v1(41.34,110.07)
  BOTTOM w0.121: v1(37.12,52.74) 37.12,51.68 37.24,51.56 37.74,51.56 37.86,51.44 37.86,51.2 37.74,51.08 37.24,51.08 37.12,50.96 37.12,50.58 37.45,50.25 38.74,50.25 38.86,50.37 38.86,57.11 38.99,57.24 39.22,57.24 39.34,57.11 39.34,49.47 39.47,49.34 39.71,49.34 39.83,49.47 39.83,51.66 39.95,51.78 40.19,51.78 40.32,51.66 40.32,49.03 40.44,48.91 41.31,48.91 41.44,49.03 41.44,51.27 39.8,52.9 39.8,59.84 40.07,60.11 40.07,63.89 35.36,68.6 35.36,80.96 38.24,83.84 38.24,85.17 38.82,85.75 38.82,98.06 39.08,98.31 39.08,98.31 39.34,98.58 39.58,98.82 39.59,98.82 41.03,100.27 41.03,100.62 41.03,109.73 41.34,110.03 v1(41.34,110.07)
ETH_RESETN: length 7.3
  TOP w0.121: U25.2 29.63,56.96 29.5,57.08 29.5,57.09 29.22,57.36 v1(29.22,57.52) ; v1(25.18,59.85) 25.05,59.99 U26.4
  BOTTOM w0.121: v1(29.22,57.52) 29.04,57.52 R391.1 27.15,59.41 25.71,59.41 25.65,59.47 25.56,59.47 v1(25.18,59.85)
ETH_RXCLK: length 5.9
  TOP w0.121: R423.1 R422.2 39.6,57.57 38.24,57.57 37.86,57.19 37.86,56.64 37.33,56.11 36.81,56.11 36.77,56.16 U25.33
ETH_RXD0: length 5.1
  TOP w0.121: U25.31 37.69,55.36 38.07,54.98 38.74,54.98 38.78,55.02 39.59,55.02 R411.2 R424.1
ETH_RXD1: length 5.2
  TOP w0.121: R425.1 R413.2 39.6,54.77 38.88,54.77 38.84,54.73 37.75,54.73 37.4,55.08 36.9,55.08 36.78,54.96 U25.30
ETH_RXD2: length 5.2
  TOP w0.121: R427.1 R419.2 39.5,53.61 37.93,53.61 37.43,54.11 36.9,54.11 36.86,54.16 U25.28
ETH_RXD3: length 5.9
  TOP w0.121: R428.1 R426.2 39.75,52.08 39.75,52.1 39.56,52.29 38.34,52.29 37.54,53.08 37.54,53.58 37.31,53.81 36.92,53.81 36.86,53.76 U25.27
ETH_RXDV: length 5.2
  TOP w0.121: R430.1 R414.2 39.39,56.09 37.84,56.09 37.5,55.76 U25.32
ETH_TXCLK: length 137.8
  TOP w0.121: v1(41.39,113.04) 41.83,113.04 42.13,112.74 42.9,112.74 43.02,112.86 43.02,112.97 43.14,113.09 43.38,113.09 43.5,112.97 43.5,112.86 43.62,112.74 43.86,112.74 43.98,112.86 43.98,112.97 44.1,113.09 44.35,113.09 44.47,112.97 44.47,112.86 44.59,112.74 44.83,112.74 44.95,112.86 44.95,112.97 45.07,113.09 45.31,113.09 45.43,112.97 45.43,112.86 45.55,112.74 51.37,112.74 51.71,113.07 61.07,113.07 61.54,113.55 81.57,113.55 82.48,112.64 86.12,112.64 86.29,112.81 v1(87.16,112.81) ; v1(37.27,58.86) 37.27,59.35 37.43,59.5 37.43,59.8 37.27,59.96 37.27,62.01 37.4,62.14 40.63,62.14 40.75,62.01 40.75,61.48 40.63,61.35 39,61.35 38.87,61.23 38.87,60.77 38.95,60.69 40.4,60.69 40.52,60.57 40.52,60.22 40.4,60.1 38.09,60.1 37.85,59.86 37.85,58.55 37.68,58.39 37.68,58 37.55,57.87 37.12,57.87 36.99,57.75 36.99,57.14 36.8,56.96 U25.35
  BOTTOM w0.121: v1(87.16,112.81) 87.16,112.38 87.03,112.25 87.03,102.85 86.88,102.7 R415.1 ; v1(41.39,113.04) 40.78,112.43 40.78,112.4 40.35,111.97 40.35,111.44 39.89,110.98 39.89,101.2 37.7,99.01 37.7,98.87 37.72,98.85 37.72,86.31 36.84,85.43 36.84,84.37 33.9,81.43 33.9,69.28 33.78,69.16 33.78,68.79 33.82,68.75 33.82,68.44 38.98,63.28 38.98,60.77 38.53,60.32 38.53,60.12 v1(37.27,58.86)
ETH_TXD0: length 141
  TOP w0.121: v1(39.64,113.78) 39.64,115.75 39.76,115.88 40.32,115.88 40.43,115.77 40.43,114.56 40.55,114.44 40.79,114.44 40.91,114.56 40.91,115.1 41.03,115.22 41.27,115.22 41.39,115.1 41.39,114.56 41.51,114.44 41.75,114.44 41.87,114.56 41.87,115.1 42,115.22 43.34,115.22 43.34,115.22 43.61,115.22 44.9,116.51 64.01,116.51 64.88,115.63 64.97,115.63 65.01,115.59 82.46,115.59 83.01,116.14 v1(85.2,116.14) ; v1(85.13,102.27) 85.53,101.87 85.53,100.77 86.19,100.11 R416.1 ; v1(36.26,57.87) U25.36
  BOTTOM w0.121: v1(85.2,116.14) 85.2,115.17 85.43,114.95 85.43,104.9 85.3,104.77 85.25,104.77 85.13,104.64 v1(85.13,102.27) ; v1(36.26,57.87) 36.26,58.9 36.29,58.93 36.29,59.7 37.76,61.16 37.76,63.18 36.83,64.11 36.33,64.61 35.62,64.61 33.04,67.19 33.04,75.49 32.92,75.61 32.73,75.61 32.6,75.74 32.6,75.97 32.73,76.09 32.88,76.09 33.01,76.22 33.01,77.29 32.88,77.42 32.56,77.42 32.44,77.54 32.44,77.78 32.56,77.9 32.92,77.9 33.04,78.02 33.04,78.26 32.92,78.38 32.56,78.38 32.44,78.5 32.44,78.74 32.56,78.86 32.92,78.86 33.04,78.98 33.04,79.23 32.92,79.35 32.56,79.35 32.44,79.47 32.44,79.71 32.56,79.83 32.92,79.83 33.04,79.95 33.04,81.02 33.02,81.04 33.02,81.5 36.17,84.64 36.17,86.76 37,87.59 37,98.39 37,99.82 38.82,101.64 38.82,110.87 39.46,111.5 39.46,112.04 40.1,112.68 40.1,113.27 40.39,113.56 40.42,113.56 40.96,114.11 41.44,114.11 41.62,114.29 41.62,115.02 41.38,115.26 40.74,115.26 39.95,114.47 39.95,114.09 v1(39.64,113.78)
ETH_TXD1: length 138.6
  TOP w0.121: v1(89.47,111.44) 89.47,112.23 89.29,112.41 88.4,112.41 88.05,112.05 87.62,112.05 87.52,111.95 86.55,111.95 86.36,111.76 80.62,111.76 79.51,112.86 70.05,112.86 70.04,112.87 69.68,112.87 69.67,112.86 65.54,112.86 64.72,112.04 40.48,112.04 v1(39.66,112.86) ; U25.37 35.6,58.23 35.85,58.48 v1(35.85,59.12) ; v1(89.15,100.22) 88.49,99.56 R417.1
  BOTTOM w0.121: v1(89.15,100.22) 89.15,100.77 89.16,100.77 89.16,105.93 89.62,106.39 89.62,110.85 89.47,111 v1(89.47,111.44) ; v1(39.66,112.86) 39.04,112.24 39.04,111.68 38.4,111.04 38.4,106.65 38.28,106.53 37.27,106.53 37.15,106.41 37.15,106.17 37.27,106.05 38.28,106.05 38.4,105.93 38.4,105.68 38.28,105.56 36.95,105.56 36.83,105.44 36.83,105.2 36.95,105.08 38.28,105.08 38.4,104.96 38.4,104.72 38.28,104.59 36.95,104.59 36.83,104.47 36.83,104.23 36.95,104.11 38.28,104.11 38.4,103.99 38.4,103.75 38.28,103.63 36.95,103.63 36.83,103.51 36.83,103.27 36.95,103.15 38.28,103.15 38.4,103.03 38.4,102.78 38.28,102.66 37.93,102.66 37.81,102.54 37.81,102.31 37.93,102.18 38.28,102.18 38.4,102.06 38.4,101.81 36.58,99.99 36.58,87.77 35.74,86.93 35.74,84.82 32.02,81.09 32.02,67.61 35.2,64.43 35.44,64.18 36.15,64.18 36.4,63.93 37.29,63.04 37.29,61.3 35.85,59.86 v1(35.85,59.12)
ETH_TXD2: length 138.6
  TOP w0.121: v1(38.59,112.1) 39.04,112.1 39.52,111.62 64.9,111.62 65.02,111.75 79.83,111.75 80.24,111.33 86.72,111.33 86.91,111.52 87.69,111.52 87.79,111.61 v1(88.71,111.61) ; R418.1 89.45,99.1 v1(89.19,99.35) ; v1(35.22,59.09) 34.98,58.86 U25.38
  BOTTOM w0.121: v1(38.59,112.1) 38.28,111.79 38.28,111.59 37.97,111.28 37.97,108.24 36.4,106.67 36.4,102.09 36.15,101.85 36.15,87.94 33.89,85.68 33.89,85.61 34.08,85.42 34.08,85.24 33.92,85.08 33.74,85.08 33.59,85.23 33.44,85.23 33.21,85 33.21,84.83 34.02,84.02 34.02,83.85 33.85,83.68 33.68,83.68 32.87,84.49 32.7,84.49 32.53,84.32 32.53,84.15 33.34,83.34 33.34,83.17 33.16,83 32.99,83 32.19,83.81 32.02,83.81 31.84,83.64 31.84,83.47 32.65,82.66 32.65,82.49 32.48,82.32 32.31,82.32 31.5,83.12 31.33,83.12 31.13,82.92 31.13,78.73 31,78.6 30.85,78.6 30.72,78.47 30.72,78.14 30.85,78.02 31,78.02 31.13,77.89 31.13,77.64 31.01,77.52 30.91,77.52 30.79,77.4 30.79,77.16 30.91,77.04 31.01,77.04 31.13,76.92 31.13,76.68 31.01,76.56 30.91,76.56 30.79,76.44 30.79,76.19 30.91,76.07 31.01,76.07 31.13,75.95 31.13,75.71 31.01,75.59 30.91,75.59 30.79,75.47 30.79,75.23 30.91,75.11 31.01,75.11 31.13,74.99 31.13,74.75 31.01,74.63 30.91,74.63 30.79,74.51 30.79,74.26 30.91,74.14 31.01,74.14 31.13,74.02 31.13,73.78 31.01,73.66 30.91,73.66 30.79,73.54 30.79,73.3 30.91,73.18 31.01,73.18 31.13,73.06 31.13,72.82 31.01,72.7 30.91,72.7 30.79,72.58 30.79,72.33 30.91,72.21 31.01,72.21 31.13,72.09 31.13,71.85 31.01,71.73 30.91,71.73 30.79,71.61 30.79,71.37 30.91,71.25 31.01,71.25 31.13,71.13 31.13,70.89 31.01,70.77 30.91,70.77 30.79,70.64 30.79,70.4 30.91,70.28 31.01,70.28 31.13,70.16 31.13,69.92 31.01,69.8 30.91,69.8 30.79,69.68 30.79,69.44 30.91,69.32 31.01,69.32 31.13,69.2 31.13,68.96 31.01,68.84 30.91,68.84 30.79,68.71 30.79,68.47 30.91,68.35 31.01,68.35 31.13,68.23 31.13,67.9 34.77,64.25 35.27,63.76 35.98,63.76 36.87,62.87 36.87,61.49 36.47,61.09 35.99,61.09 35.65,61.43 35.37,61.43 35.22,61.28 v1(35.22,59.09) ; v1(88.71,111.61) 88.71,110.68 89.17,110.22 89.17,106.74 88.71,106.29 88.71,99.83 v1(89.19,99.35)
ETH_TXD3: length 142.5
  TOP w0.121: U25.39 34.58,59.25 35.06,59.73 35.72,59.73 36.33,60.34 v1(36.33,61.58) ; R420.1 85.02,99.2 v1(85.02,99.99) ; v1(84.54,117.11) 73.69,117.11 73.12,116.53 65.38,116.53 64.55,117.36 43.37,117.36 v1(41.69,115.68)
  BOTTOM w0.121: v1(84.54,117.11) 84.54,115.23 85,114.77 85,105.32 84.69,105.01 84.69,102.09 85.13,101.65 85.13,100.09 v1(85.02,99.99) ; v1(41.69,115.68) 40.56,115.68 39.05,114.18 39.05,113.27 37.55,111.77 37.55,108.41 35.98,106.84 35.98,102.27 35.73,102.02 35.73,88.12 30.13,82.52 30.13,76.3 30.01,76.18 29.68,76.18 29.55,76.05 29.55,75.83 29.68,75.7 30.01,75.7 30.13,75.58 30.13,75.34 30.01,75.22 29.33,75.22 29.21,75.1 29.21,74.85 29.33,74.73 30.01,74.73 30.13,74.61 30.13,74.37 30.01,74.25 29.33,74.25 29.21,74.13 29.21,73.89 29.33,73.77 30.01,73.77 30.13,73.65 30.13,73.41 30.01,73.29 29.33,73.29 29.21,73.17 29.21,72.92 29.33,72.8 30.01,72.8 30.13,72.68 30.13,72.44 30.01,72.32 29.33,72.32 29.21,72.2 29.21,71.96 29.33,71.84 30.01,71.84 30.13,71.72 30.13,71.48 30.01,71.36 29.33,71.36 29.21,71.24 29.21,70.99 29.33,70.87 30.01,70.87 30.13,70.75 30.13,70.51 30.01,70.39 29.33,70.39 29.21,70.27 29.21,70.03 29.33,69.91 30.01,69.91 30.13,69.79 30.13,69.55 30.01,69.43 29.33,69.43 29.21,69.3 29.21,69.06 29.33,68.94 30.01,68.94 30.13,68.82 30.13,68.29 34.34,64.08 35.09,63.33 35.8,63.33 36.41,62.72 36.41,62.1 36.33,62.02 v1(36.33,61.58)
ETH_TXEN: length 140.9
  TOP w0.121: R421.1 85.6,98.82 85.6,99.43 85.47,99.56 85.47,100.17 84.93,100.7 84.93,101.41 84.69,101.66 84.69,108.12 82.79,110.02 80.1,110.02 80.1,110.02 79.75,110.02 79.3,110.47 65.55,110.47 65.36,110.27 51.14,110.27 50.63,109.76 48.69,109.76 48.57,109.64 48.57,107.48 48.44,107.35 48.22,107.35 48.09,107.48 48.09,109.64 47.97,109.76 47.73,109.76 47.61,109.64 47.61,106.41 47.49,106.29 47.24,106.29 47.12,106.41 47.12,109.64 47,109.76 46.76,109.76 46.64,109.64 46.64,106.41 46.52,106.29 46.28,106.29 46.16,106.41 46.16,109.64 46.04,109.76 45.8,109.76 45.68,109.64 45.68,106.41 45.56,106.29 45.31,106.29 45.19,106.41 45.19,109.64 45.07,109.76 44.7,109.76 43.65,110.81 v1(41.49,110.81) ; U25.34 v1(37.15,56.56)
  BOTTOM w0.121: v1(37.15,56.56) 37.46,56.87 37.46,56.87 37.98,57.39 38.26,57.39 39.38,58.5 39.38,60.01 39.65,60.28 39.65,63.71 34.93,68.43 34.93,81.14 37.81,84.01 37.81,85.34 38.4,85.93 38.4,98.23 38.65,98.49 38.65,98.49 39.04,98.88 39.4,99.24 39.4,99.24 40.61,100.44 40.61,110.36 41.05,110.81 v1(41.49,110.81)
ETHER_D0N: length 70.8
  TOP w0.095: v1(26.83,50.71) 27.22,51.09 28.49,51.09 28.99,51.6 28.99,52.7 29.3,53.02 29.47,53.02 29.53,52.96 U25.12
  BOTTOM w0.095: J15.10 38.52,13.37 38.52,13.75 39,14.24 40.69,14.24 40.93,13.99 40.93,12.36 39.03,10.45 28.49,10.45 23.15,15.79 23.15,49.95 24.65,51.45 26.51,51.45 26.66,51.3 26.88,51.3 27.09,51.09 27.09,50.96 v1(26.83,50.71)
ETHER_D0P: length 70.9
  TOP w0.095: U25.11 29.53,53.36 29.47,53.29 29.19,53.29 28.71,52.82 28.71,51.71 28.37,51.37 27.19,51.37 v1(26.83,51.73)
  BOTTOM w0.095: J15.9 38.64,14.52 40.8,14.52 41.21,14.11 41.21,12.24 39.14,10.17 28.37,10.17 22.87,15.67 22.87,50.06 24.53,51.73 v1(26.83,51.73)
ETHER_D1N: length 71
  TOP w0.095: v1(30.14,49.19) 29.65,49.67 29.65,50.21 30,50.56 30.27,50.56 30.4,50.43 31.38,50.43 31.76,50.81 31.76,51.54 31.78,51.57 U25.15
  BOTTOM w0.095: J15.8 35.98,12.61 35.72,12.86 35.72,13.25 36.4,13.93 37.2,13.93 38.01,13.12 38.01,11.98 37.4,11.37 28.85,11.37 24.42,15.8 24.42,22.64 25.06,23.28 28.37,23.28 30.16,25.07 30.16,29.11 28.53,30.74 24.85,30.74 24.42,31.17 24.42,41.06 29.63,46.27 29.63,49.08 29.74,49.19 v1(30.14,49.19)
ETHER_D1P: length 71.1
  TOP w0.095: v1(28.87,49.19) 29.37,49.69 29.37,50.32 29.89,50.84 30.39,50.84 30.52,50.71 31.26,50.71 31.48,50.92 31.48,51.48 31.38,51.57 U25.14
  BOTTOM w0.095: v1(28.87,49.19) 29.35,48.7 29.35,46.38 24.14,41.17 24.14,31.05 24.73,30.46 28.42,30.46 29.88,28.99 29.88,25.18 28.26,23.56 24.94,23.56 24.14,22.76 24.14,15.68 28.74,11.09 37.52,11.09 38.29,11.86 38.29,13.23 37.32,14.21 36.41,14.21 J15.7
ETHER_D2N: length 71
  TOP w0.095: v1(33.82,49.19) 33.46,49.19 33.33,49.31 33.33,49.66 33.04,49.95 32.22,49.95 32.04,50.13 32.04,50.38 32.22,50.56 32.65,50.56 32.96,50.86 32.96,52.05 U25.18
  BOTTOM w0.095: v1(33.82,49.19) 33.42,49.19 33.32,49.09 33.32,39.79 32.79,39.25 27.84,39.25 27.75,39.16 27.75,36.35 27.84,36.26 33.99,36.26 34.41,35.84 34.41,25.82 34.66,25.56 35.88,25.56 36.13,25.31 36.13,22.77 35.88,22.52 34.66,22.52 34.41,22.26 34.41,20.99 34.66,20.74 41.69,20.74 41.95,20.48 41.95,18.97 41.53,18.55 34.5,18.55 34.41,18.46 34.41,14.4 34.2,14.19 J15.6
ETHER_D2P: length 71.1
  TOP w0.095: v1(32.55,49.19) 32.92,49.19 33.05,49.31 33.05,49.54 32.92,49.67 32.1,49.67 31.76,50.01 31.76,50.49 32.1,50.84 32.53,50.84 32.68,50.98 32.68,51.99 U25.17
  BOTTOM w0.095: J15.5 32.93,14.52 33.18,14.26 33.88,14.26 34.13,14.52 34.13,18.58 34.38,18.83 41.41,18.83 41.67,19.09 41.67,20.37 41.58,20.46 34.55,20.46 34.13,20.88 34.13,22.38 34.55,22.8 35.76,22.8 35.85,22.89 35.85,25.19 35.76,25.28 34.55,25.28 34.13,25.7 34.13,35.72 33.88,35.98 27.72,35.98 27.47,36.23 27.47,39.28 27.72,39.53 32.68,39.53 33.04,39.9 33.04,49.09 32.95,49.19 v1(32.55,49.19)
ETHER_D3N: length 70.9
  TOP w0.095: v1(36.36,49.19) 35.86,49.69 35.86,50.07 35.91,50.13 35.91,50.7 35.62,50.99 35.03,50.99 34.84,50.8 34.37,50.8 34.12,51.04 34.12,52.02 U25.21
  BOTTOM w0.095: v1(36.36,49.19) 35.96,49.23 35.85,49.14 35.85,49.06 35.85,48.4 35.59,48.14 34.72,48.14 34.3,48.56 34.3,49.45 34.08,49.67 31.79,49.67 31.53,49.41 31.53,41.69 31,41.16 26.67,41.16 26.58,41.07 26.58,33.72 26.83,33.46 31.51,33.46 32.07,32.9 32.07,22.29 31.66,21.88 25.82,21.88 25.56,21.63 25.56,18.48 25.82,18.22 31.52,18.22 31.94,17.81 31.94,14.53 31.27,13.85 31.25,13.85 31.15,13.75 31.15,13.12 J15.4
ETHER_D3P: length 70.6
  TOP w0.095: v1(35.09,49.31) 35.58,49.8 35.58,50.19 35.64,50.25 35.64,50.58 35.51,50.71 35.15,50.71 34.96,50.52 34.25,50.52 33.84,50.92 33.84,52.02 U25.20
  BOTTOM w0.095: v1(35.09,49.31) 35.49,49.27 35.58,49.17 35.57,49.07 35.57,48.52 35.47,48.42 34.84,48.42 34.58,48.68 34.58,49.57 34.2,49.95 31.67,49.95 31.25,49.53 31.25,41.81 30.88,41.44 26.55,41.44 26.3,41.19 26.3,33.6 26.72,33.18 31.39,33.18 31.79,32.79 31.79,22.4 31.54,22.16 25.7,22.16 25.28,21.74 25.28,18.36 25.7,17.94 31.41,17.94 31.66,17.69 31.66,14.64 31.15,14.13 30.52,14.13 30.39,14.26 J15.3
